(* Logix 5000 project; controller Electronic_Displays vendor 1 type 14 code 65 rev 17.4; software revision 17.01; part 2 of 9 *)
(* tags used below, declared in another part *)
   EDV : LEDSIGN;
   ENABLE : DINT;

ADD_ON_INSTRUCTION ExpertSign   (* revision 1.0, ExecuteEnableInFalse *)
// Expert Mode
// Send Your Own
// Packets
// Revision note:
// Original Release
// 11-01-2012
// c.elston
VAR_IN_OUT
   ExpertPacket1 : STRING; {required}   // Raw Packet1 to be sent to sign for the expert users. (82 Characters max)
   ExpertPacket2 : STRING; {required}   // Raw Packet2 to be sent to sign for the expert users. (82 Characters max)
   ExpertPacket3 : STRING; {required}   // Raw Packet3 to be sent to sign for the expert users. (82 Characters max)
   ExpertPacket4 : STRING; {required}   // Raw Packet4 to be sent to sign for the expert users. (82 Characters max)
   ExpertPacket5 : STRING; {required}   // Raw Packet5 to be sent to sign for the expert users. (82 Characters max)
   ExpertPacket6 : STRING; {required}   // Raw Packet6 to be sent to sign for the expert users. (82 Characters max)
END_VAR
VAR_OUTPUT
   EN : BOOL; {visible}   // Instruction Interface Enable Bit
   DN : BOOL; {visible}   // Instruction Interface Done Bit
   ER : BOOL; {visible}   // Instruction Interface Error Bit
   IP : BOOL; {visible}   // Instruction Interface InProcess Bit
END_VAR
VAR_IN_OUT
   map_SignInput : SINT[32]; {required}   // Ethernet/IP LEDSIGN.I Data I/O Mapping
   map_SignOutput : SINT[496]; {required}   // Ethernet/IP LEDSIGN.O Data I/O Mapping
   Packet1Sent : STRING; {required}   // The actual packet sent to the sign (Packet1)
   Packet2Sent : STRING; {required}   // The actual packet sent to the sign (Packet2)
   Packet3Sent : STRING; {required}   // The actual packet sent to the sign (Packet3)
   Packet4Sent : STRING; {required}   // The actual packet sent to the sign (Packet4)
   Packet5Sent : STRING; {required}   // The actual packet sent to the sign (Packet5)
   Packet6Sent : STRING; {required}   // The actual packet sent to the sign (Packet6)
END_VAR
VAR
   SEQ : DINT;   // Sequence Number
   OktoCycle : BOOL;   // Ok to Cycle
   InCycle : BOOL;   // Incycle
   Error : BOOL;   // Error
   Enabled : BOOL;   // Enable ON Bit
   Done : BOOL;   // Done
   Disabled : BOOL;   // Disabled OFF Bit
   SignNULL : STRING;
   TotalPacketCount : DINT[7];   // Total Character Count
   Select : DINT;   // Packet Array Select
   PacketMax : DINT := 82;   // Max Packet Count
   PacketCount : DINT[7];
   Packet6Offset : DINT;
   Packet5Offset : DINT;
   Packet4Offset : DINT;
   Packet3Offset : DINT;
   Packet2Offset : DINT;
   Packet1Offset : DINT;
   Packet : STRING[7];   // Packet Array to send to sign
   SignExpertPacket6 : STRING;
   SignExpertPacket5 : STRING;
   SignExpertPacket4 : STRING;
   SignExpertPacket3 : STRING;
   SignExpertPacket2 : STRING;
   SignExpertPacket1 : STRING;
END_VAR

ROUTINE EnableInFalse   (* ladder *)
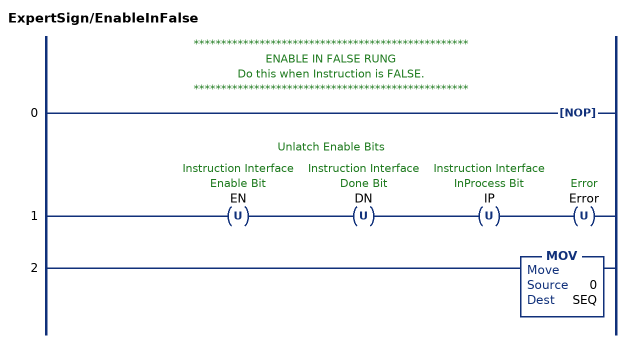
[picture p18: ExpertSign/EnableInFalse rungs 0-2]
   // **************************************************
   // ENABLE IN FALSE RUNG
   // Do this when Instruction is FALSE.
   // **************************************************
   0: NOP();
   // Unlatch Enable Bits
   1: OTU(EN)OTU(DN)OTU(IP)OTU(Error);
   2: MOV(0,SEQ);
END_ROUTINE

ROUTINE Logic   (* ladder *)
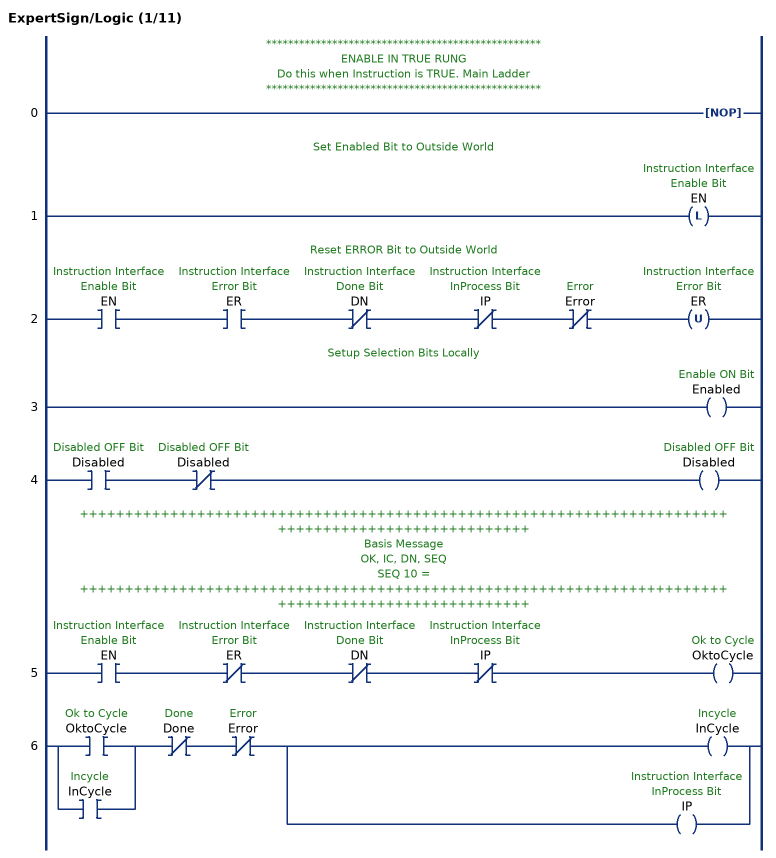
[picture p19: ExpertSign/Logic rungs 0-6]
   // **************************************************
   // ENABLE IN TRUE RUNG
   // Do this when Instruction is TRUE. Main Ladder
   // **************************************************
   0: NOP();
   // Set Enabled Bit to Outside World
   1: OTL(EN);
   // Reset ERROR Bit to Outside World
   2: XIC(EN)XIC(ER)XIO(DN)XIO(IP)XIO(Error)OTU(ER);
   // Setup Selection Bits Locally
   3: OTE(Enabled);
   4: XIC(Disabled)XIO(Disabled)OTE(Disabled);
   // ++++++++++++++++++++++++++++++++++++++++++++++++++++++++++++++++++++++++++++++++++++++++++++++++++++
   // Basis Message
   // OK, IC, DN, SEQ
   // SEQ 10 =
   // ++++++++++++++++++++++++++++++++++++++++++++++++++++++++++++++++++++++++++++++++++++++++++++++++++++
   5: XIC(EN)XIO(ER)XIO(DN)XIO(IP)OTE(OktoCycle);
   6: [XIC(OktoCycle) ,XIC(InCycle) ]XIO(Done)XIO(Error)[OTE(InCycle) ,OTE(IP) ];
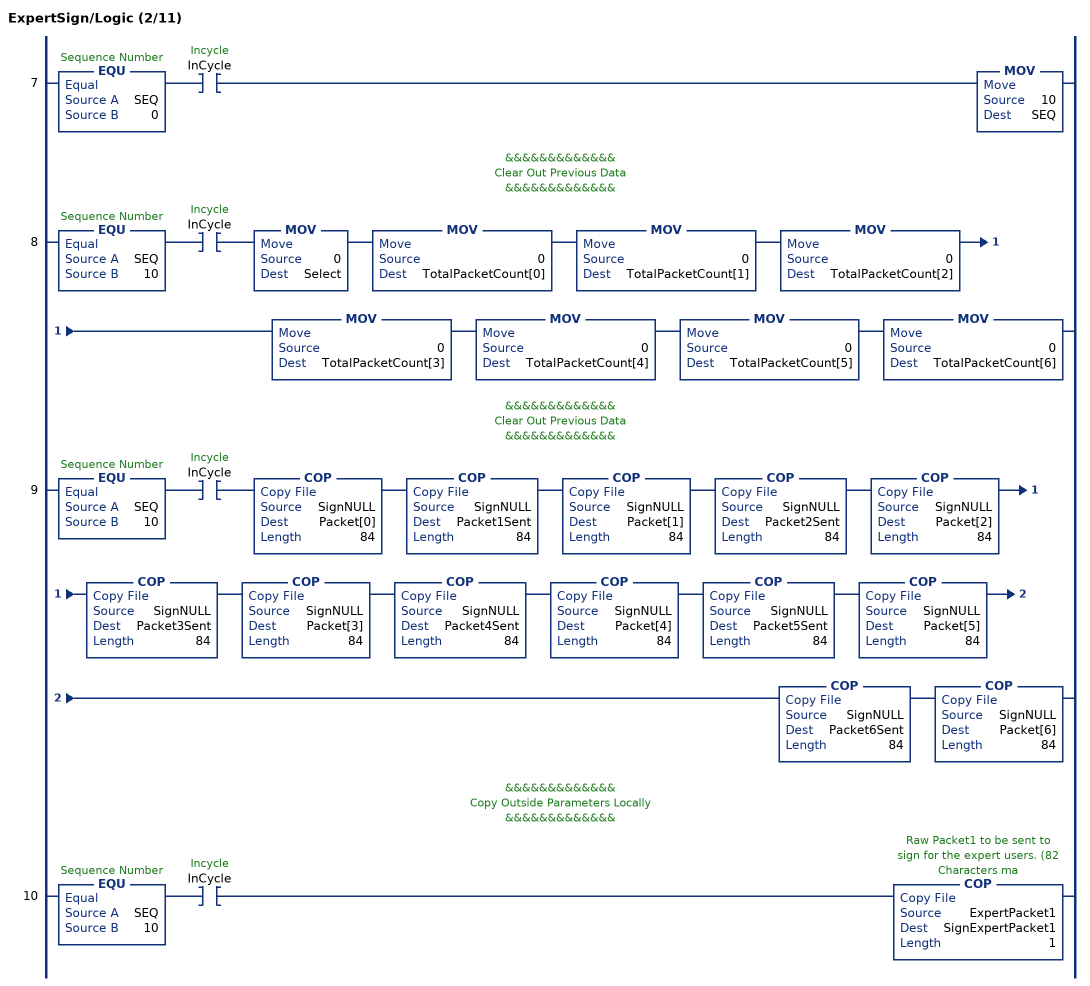
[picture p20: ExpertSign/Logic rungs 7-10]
   7: EQU(SEQ,0)XIC(InCycle)MOV(10,SEQ);
   // &&&&&&&&&&&&&
   // Clear Out Previous Data
   // &&&&&&&&&&&&&
   8: EQU(SEQ,10)XIC(InCycle)MOV(0,Select)MOV(0,TotalPacketCount[0])MOV(0,TotalPacketCount[1])MOV(0,TotalPacketCount[2])MOV(0,TotalPacketCount[3])MOV(0,TotalPacketCount[4])MOV(0,TotalPacketCount[5])MOV(0,TotalPacketCount[6]);
   // &&&&&&&&&&&&&
   // Clear Out Previous Data
   // &&&&&&&&&&&&&
   9: EQU(SEQ,10)XIC(InCycle)COP(SignNULL,Packet[0],84)COP(SignNULL,Packet1Sent,84)COP(SignNULL,Packet[1],84)COP(SignNULL,Packet2Sent,84)COP(SignNULL,Packet[2],84)COP(SignNULL,Packet3Sent,84)COP(SignNULL,Packet[3],84)COP(SignNULL,Packet4Sent,84)COP(SignNULL,Packet[4],84)COP(SignNULL,Packet5Sent,84)COP(SignNULL,Packet[5],84)COP(SignNULL,Packet6Sent,84)COP(SignNULL,Packet[6],84);
   // &&&&&&&&&&&&&
   // Copy Outside Parameters Locally
   // &&&&&&&&&&&&&
   10: EQU(SEQ,10)XIC(InCycle)COP(ExpertPacket1,SignExpertPacket1,1);
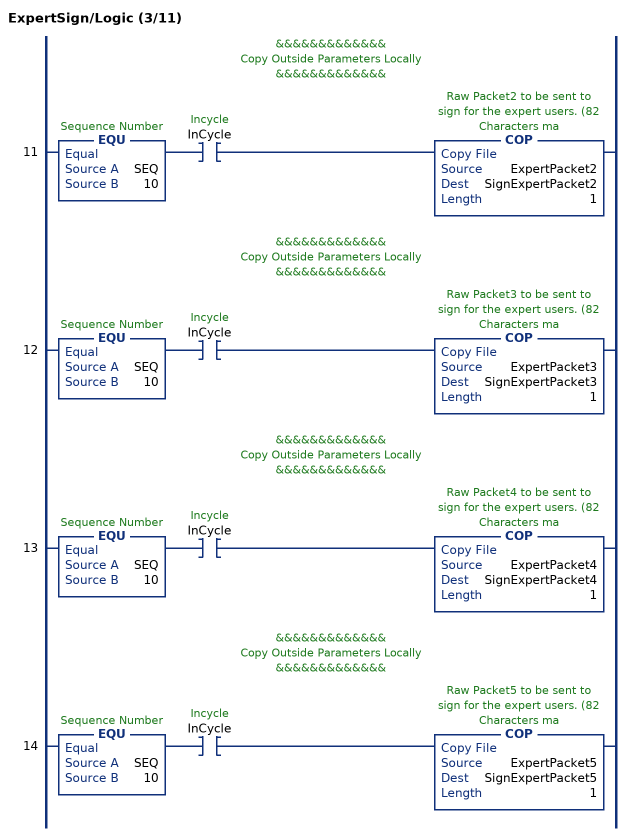
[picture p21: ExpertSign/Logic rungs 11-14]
   // &&&&&&&&&&&&&
   // Copy Outside Parameters Locally
   // &&&&&&&&&&&&&
   11: EQU(SEQ,10)XIC(InCycle)COP(ExpertPacket2,SignExpertPacket2,1);
   // &&&&&&&&&&&&&
   // Copy Outside Parameters Locally
   // &&&&&&&&&&&&&
   12: EQU(SEQ,10)XIC(InCycle)COP(ExpertPacket3,SignExpertPacket3,1);
   // &&&&&&&&&&&&&
   // Copy Outside Parameters Locally
   // &&&&&&&&&&&&&
   13: EQU(SEQ,10)XIC(InCycle)COP(ExpertPacket4,SignExpertPacket4,1);
   // &&&&&&&&&&&&&
   // Copy Outside Parameters Locally
   // &&&&&&&&&&&&&
   14: EQU(SEQ,10)XIC(InCycle)COP(ExpertPacket5,SignExpertPacket5,1);
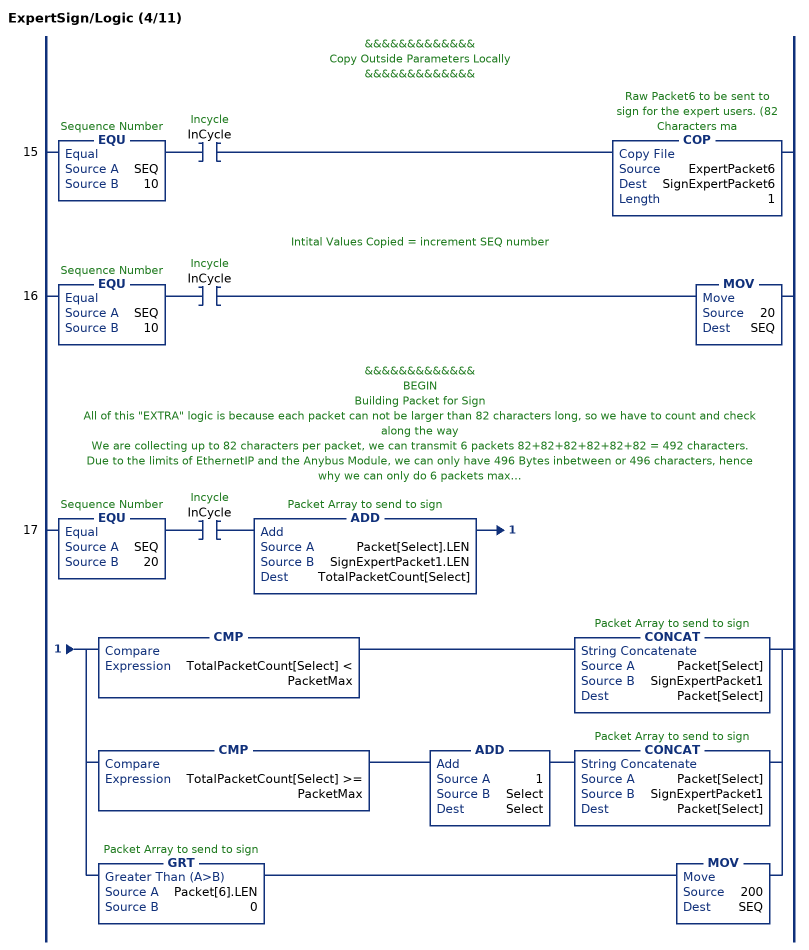
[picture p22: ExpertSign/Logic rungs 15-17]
   // &&&&&&&&&&&&&
   // Copy Outside Parameters Locally
   // &&&&&&&&&&&&&
   15: EQU(SEQ,10)XIC(InCycle)COP(ExpertPacket6,SignExpertPacket6,1);
   // Intital Values Copied = increment SEQ number
   16: EQU(SEQ,10)XIC(InCycle)MOV(20,SEQ);
   // &&&&&&&&&&&&&
   // BEGIN
   // Building Packet for Sign
   // All of this "EXTRA" logic is because each packet can not be larger than 82 characters long, so we have to count and check along the way
   // We are collecting up to 82 characters per packet, we can transmit 6 packets 82+82+82+82+82+82 = 492 characters.
   // Due to the limits of EthernetIP and the Anybus Module, we can only have 496 Bytes inbetween or 496 characters, hence why we can only do 6 packets max.
   // Once we exceed this, we will fault and ERROR trap any windy typing people.
   // In this instruction below, it's so small, we are only using 3 packets max.
   // &&&&&&&&&&&&&
   17: EQU(SEQ,20)XIC(InCycle)ADD(Packet[Select].LEN,SignExpertPacket1.LEN,TotalPacketCount[Select])[CMP(TotalPacketCount[Select] < PacketMax) CONCAT(Packet[Select],SignExpertPacket1,Packet[Select]) ,CMP(TotalPacketCount[Select] >= PacketMax) ADD(1,Select,Select) CONCAT(Packet[Select],SignExpertPacket1,Packet[Select]) ,GRT(Packet[6].LEN,0) MOV(200,SEQ) ];
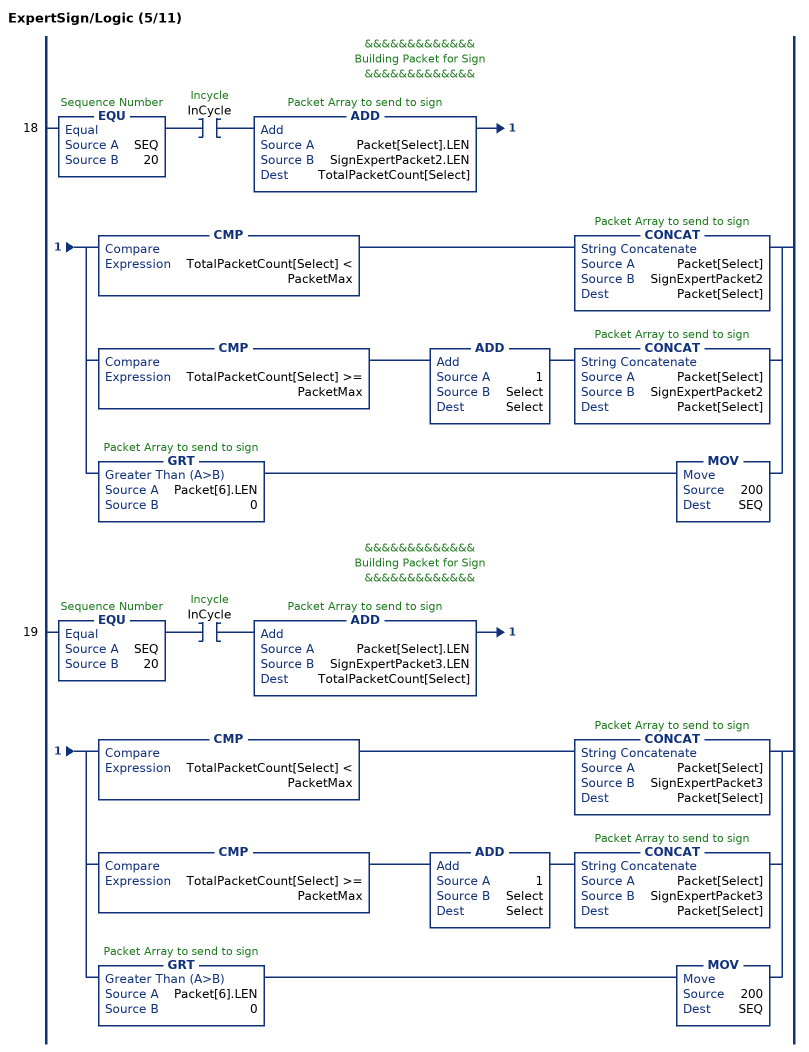
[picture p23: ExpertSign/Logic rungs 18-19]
   // &&&&&&&&&&&&&
   // Building Packet for Sign
   // &&&&&&&&&&&&&
   18: EQU(SEQ,20)XIC(InCycle)ADD(Packet[Select].LEN,SignExpertPacket2.LEN,TotalPacketCount[Select])[CMP(TotalPacketCount[Select] < PacketMax) CONCAT(Packet[Select],SignExpertPacket2,Packet[Select]) ,CMP(TotalPacketCount[Select] >= PacketMax) ADD(1,Select,Select) CONCAT(Packet[Select],SignExpertPacket2,Packet[Select]) ,GRT(Packet[6].LEN,0) MOV(200,SEQ) ];
   // &&&&&&&&&&&&&
   // Building Packet for Sign
   // &&&&&&&&&&&&&
   19: EQU(SEQ,20)XIC(InCycle)ADD(Packet[Select].LEN,SignExpertPacket3.LEN,TotalPacketCount[Select])[CMP(TotalPacketCount[Select] < PacketMax) CONCAT(Packet[Select],SignExpertPacket3,Packet[Select]) ,CMP(TotalPacketCount[Select] >= PacketMax) ADD(1,Select,Select) CONCAT(Packet[Select],SignExpertPacket3,Packet[Select]) ,GRT(Packet[6].LEN,0) MOV(200,SEQ) ];
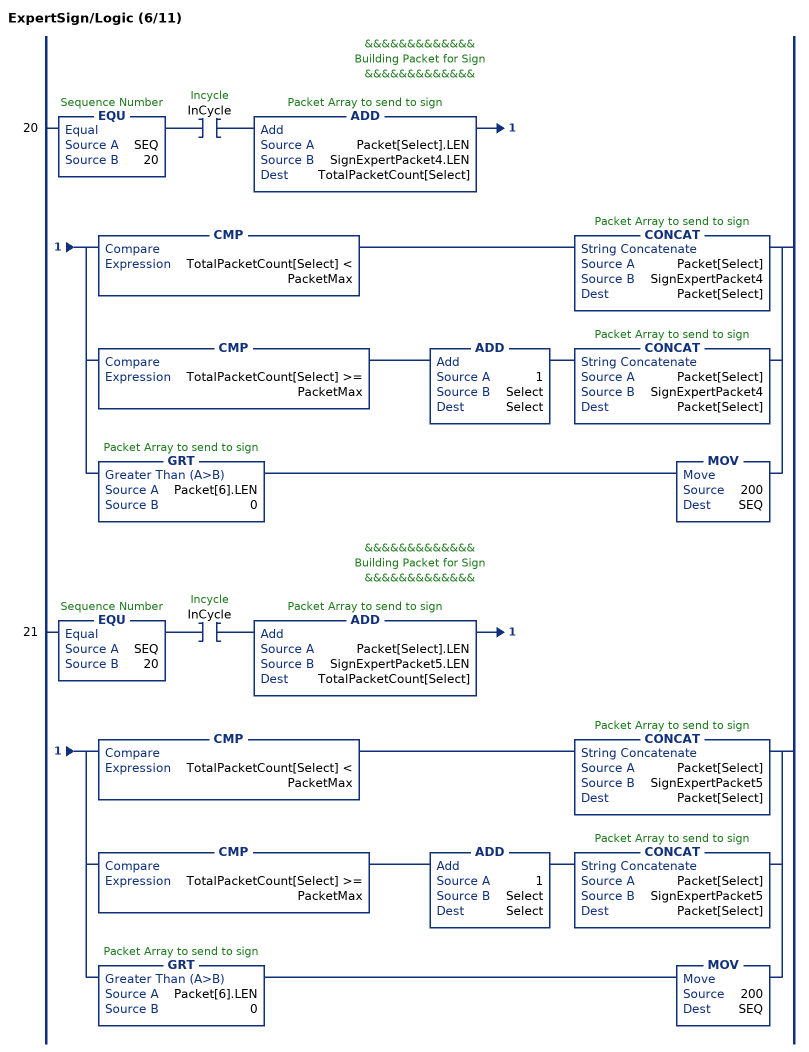
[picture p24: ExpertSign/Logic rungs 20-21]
   // &&&&&&&&&&&&&
   // Building Packet for Sign
   // &&&&&&&&&&&&&
   20: EQU(SEQ,20)XIC(InCycle)ADD(Packet[Select].LEN,SignExpertPacket4.LEN,TotalPacketCount[Select])[CMP(TotalPacketCount[Select] < PacketMax) CONCAT(Packet[Select],SignExpertPacket4,Packet[Select]) ,CMP(TotalPacketCount[Select] >= PacketMax) ADD(1,Select,Select) CONCAT(Packet[Select],SignExpertPacket4,Packet[Select]) ,GRT(Packet[6].LEN,0) MOV(200,SEQ) ];
   // &&&&&&&&&&&&&
   // Building Packet for Sign
   // &&&&&&&&&&&&&
   21: EQU(SEQ,20)XIC(InCycle)ADD(Packet[Select].LEN,SignExpertPacket5.LEN,TotalPacketCount[Select])[CMP(TotalPacketCount[Select] < PacketMax) CONCAT(Packet[Select],SignExpertPacket5,Packet[Select]) ,CMP(TotalPacketCount[Select] >= PacketMax) ADD(1,Select,Select) CONCAT(Packet[Select],SignExpertPacket5,Packet[Select]) ,GRT(Packet[6].LEN,0) MOV(200,SEQ) ];
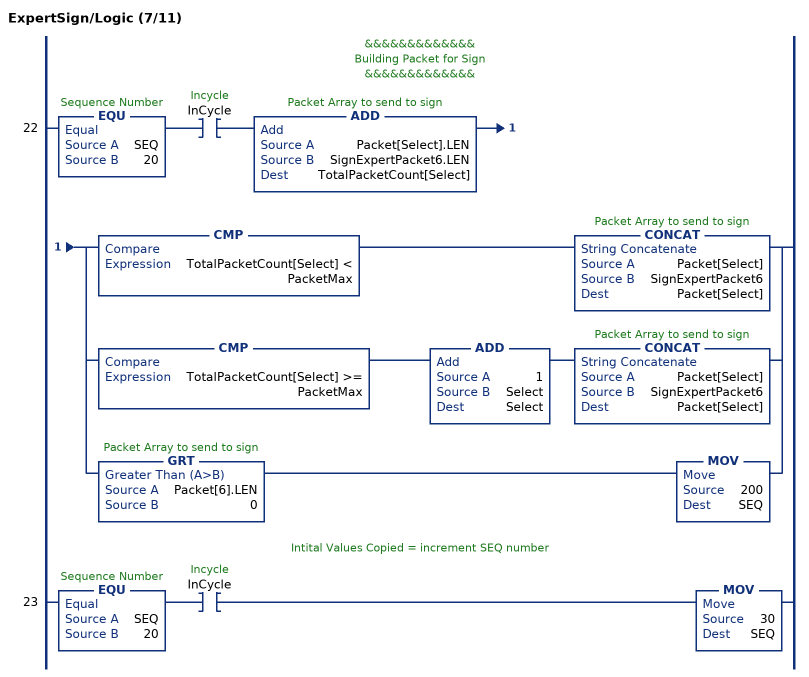
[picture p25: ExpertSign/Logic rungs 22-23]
   // &&&&&&&&&&&&&
   // Building Packet for Sign
   // &&&&&&&&&&&&&
   22: EQU(SEQ,20)XIC(InCycle)ADD(Packet[Select].LEN,SignExpertPacket6.LEN,TotalPacketCount[Select])[CMP(TotalPacketCount[Select] < PacketMax) CONCAT(Packet[Select],SignExpertPacket6,Packet[Select]) ,CMP(TotalPacketCount[Select] >= PacketMax) ADD(1,Select,Select) CONCAT(Packet[Select],SignExpertPacket6,Packet[Select]) ,GRT(Packet[6].LEN,0) MOV(200,SEQ) ];
   // Intital Values Copied = increment SEQ number
   23: EQU(SEQ,20)XIC(InCycle)MOV(30,SEQ);
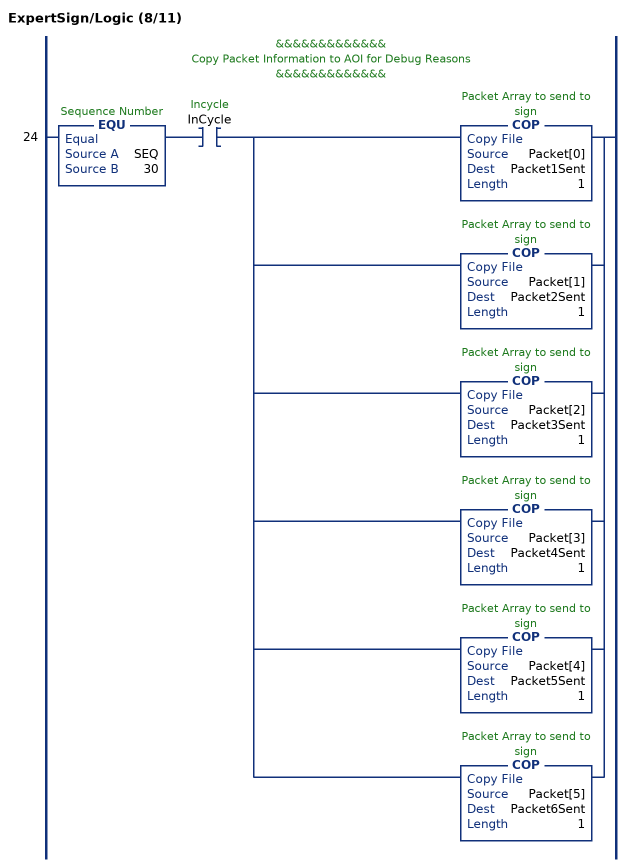
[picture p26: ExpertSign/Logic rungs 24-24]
   // &&&&&&&&&&&&&
   // Copy Packet Information to AOI for Debug Reasons
   // &&&&&&&&&&&&&
   24: EQU(SEQ,30)XIC(InCycle)[COP(Packet[0],Packet1Sent,1) ,COP(Packet[1],Packet2Sent,1) ,COP(Packet[2],Packet3Sent,1) ,COP(Packet[3],Packet4Sent,1) ,COP(Packet[4],Packet5Sent,1) ,COP(Packet[5],Packet6Sent,1) ];
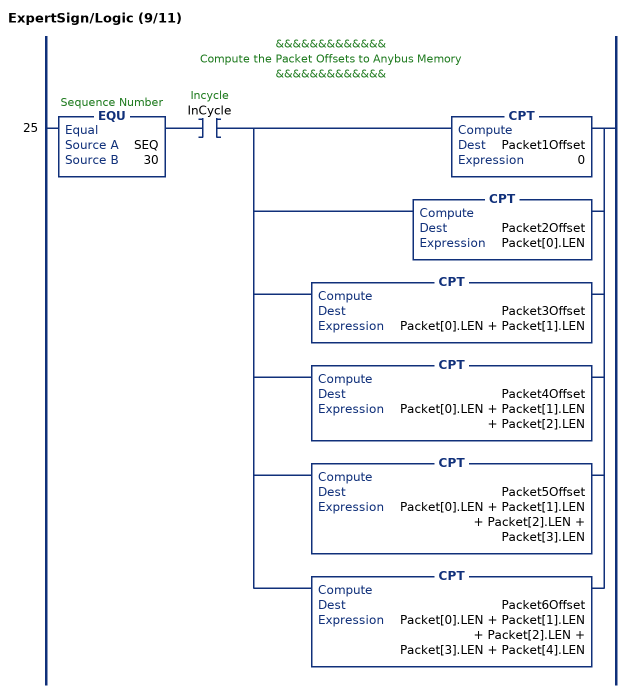
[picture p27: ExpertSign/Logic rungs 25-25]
   // &&&&&&&&&&&&&
   // Compute the Packet Offsets to Anybus Memory
   // &&&&&&&&&&&&&
   25: EQU(SEQ,30)XIC(InCycle)[CPT(Packet1Offset,0) ,CPT(Packet2Offset,Packet[0].LEN) ,CPT(Packet3Offset,Packet[0].LEN + Packet[1].LEN) ,CPT(Packet4Offset,Packet[0].LEN + Packet[1].LEN + Packet[2].LEN) ,CPT(Packet5Offset,Packet[0].LEN + Packet[1].LEN + Packet[2].LEN + Packet[3].LEN) ,CPT(Packet6Offset,Packet[0].LEN + Packet[1].LEN + Packet[2].LEN + Packet[3].LEN + Packet[4].LEN) ];
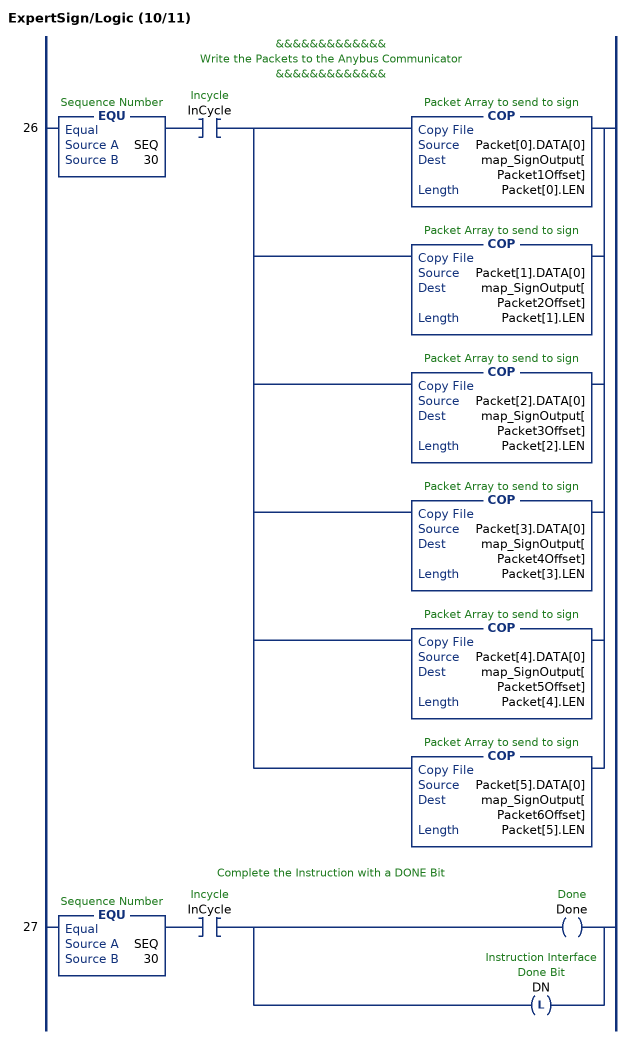
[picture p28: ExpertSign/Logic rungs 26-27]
   // &&&&&&&&&&&&&
   // Write the Packets to the Anybus Communicator
   // &&&&&&&&&&&&&
   26: EQU(SEQ,30)XIC(InCycle)[COP(Packet[0].DATA[0],map_SignOutput[Packet1Offset],Packet[0].LEN) ,COP(Packet[1].DATA[0],map_SignOutput[Packet2Offset],Packet[1].LEN) ,COP(Packet[2].DATA[0],map_SignOutput[Packet3Offset],Packet[2].LEN) ,COP(Packet[3].DATA[0],map_SignOutput[Packet4Offset],Packet[3].LEN) ,COP(Packet[4].DATA[0],map_SignOutput[Packet5Offset],Packet[4].LEN) ,COP(Packet[5].DATA[0],map_SignOutput[Packet6Offset],Packet[5].LEN) ];
   // Complete the Instruction with a DONE Bit
   27: EQU(SEQ,30)XIC(InCycle)[OTE(Done) ,OTL(DN) ];
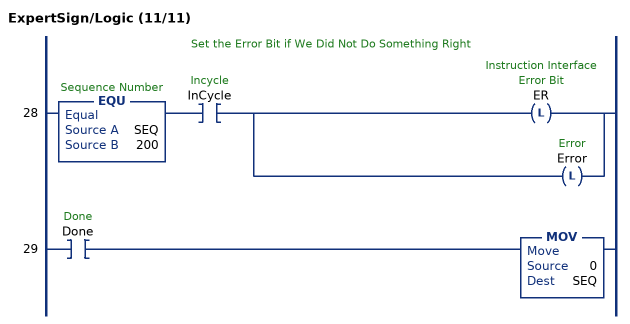
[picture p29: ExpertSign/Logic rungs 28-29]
   // Set the Error Bit if We Did Not Do Something Right
   28: EQU(SEQ,200)XIC(InCycle)[OTL(ER) ,OTL(Error) ];
   29: XIC(Done)MOV(0,SEQ);
END_ROUTINE
END_ADD_ON_INSTRUCTION

ADD_ON_INSTRUCTION NumberSign   (* revision 1.0, ExecuteEnableInFalse *)
// Number Sign
// Send only Numbers
// Revision note:
// Original Release
// 03-30-2013
// c.elston
VAR_IN_OUT
   Address : STRING; {required}   // "01" = address 01 "02" = address 02 etc...(see protocol)
   NumberValue : DINT; {required}   // Actual number value (DINT Format)
END_VAR
VAR_OUTPUT
   EN : BOOL; {visible}   // Instruction Interface Enable Bit
   DN : BOOL; {visible}   // Instruction Interface Done Bit
   ER : BOOL; {visible}   // Instruction Interface Error Bit
   IP : BOOL; {visible}   // Instruction Interface InProcess Bit
END_VAR
VAR_IN_OUT
   map_SignInput : SINT[32]; {required}   // Ethernet/IP LEDSIGN.I Data I/O Mapping
   map_SignOutput : SINT[496]; {required}   // Ethernet/IP LEDSIGN.O Data I/O Mapping
   PacketSent : STRING; {required}   // The actual packet sent to the sign.
END_VAR
VAR
   SEQ : DINT;   // Sequence Number
   OktoCycle : BOOL;   // Ok to Cycle
   InCycle : BOOL;   // Incycle
   Error : BOOL;   // Error
   Enabled : BOOL;   // Enable ON Bit
   Done : BOOL;   // Done
   Disabled : BOOL;   // Disabled OFF Bit
   SignETX : STRING := '$03';   // DO NOT EDIT = $03 the number sign protocol is different than EDV signs
   SignAddress : STRING;
   SignSTX : STRING := '$02';   // DO NOT EDIT = $02 the number sign protocol is different than EDV signs
   SignNULL : STRING;
   TotalPacketCount : DINT[7];   // Total Character Count
   Select : DINT;   // Packet Array Select
   PacketMax : DINT := 82;   // Max Packet Count
   PacketCount : DINT[7];
   Packet6Offset : DINT;
   Packet5Offset : DINT;
   Packet4Offset : DINT;
   Packet3Offset : DINT;
   Packet2Offset : DINT;
   Packet1Offset : DINT;
   Packet : STRING[7];   // Packet Array to send to sign
   SignNumberValue : DINT;
   SignVariable1Value : STRING;
   SignNumberValue1 : STRING;
   SignNumberValueSTRING : STRING;
END_VAR

ROUTINE EnableInFalse   (* ladder *)
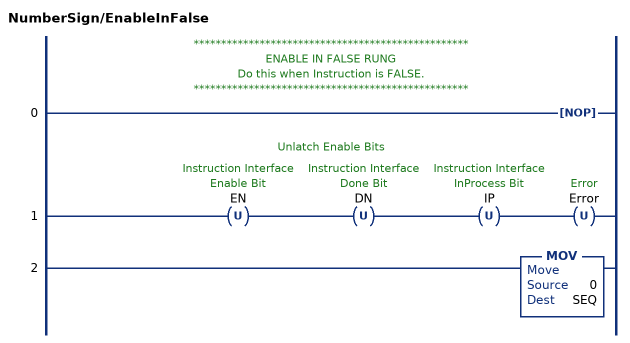
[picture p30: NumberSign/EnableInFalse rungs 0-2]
   // **************************************************
   // ENABLE IN FALSE RUNG
   // Do this when Instruction is FALSE.
   // **************************************************
   0: NOP();
   // Unlatch Enable Bits
   1: OTU(EN)OTU(DN)OTU(IP)OTU(Error);
   2: MOV(0,SEQ);
END_ROUTINE

ROUTINE Logic   (* ladder *)
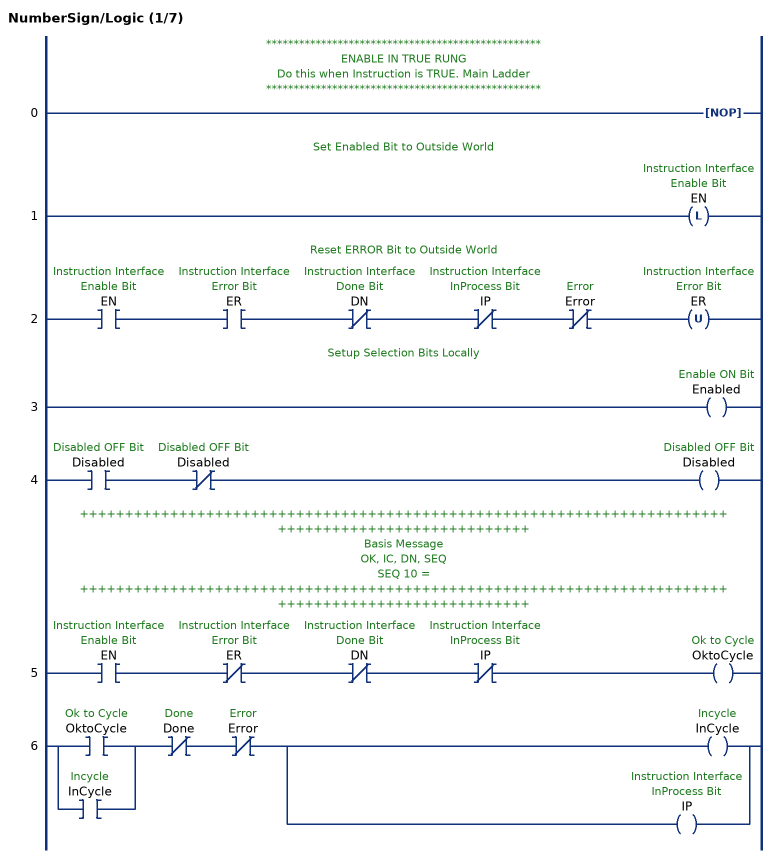
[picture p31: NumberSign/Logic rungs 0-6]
   // **************************************************
   // ENABLE IN TRUE RUNG
   // Do this when Instruction is TRUE. Main Ladder
   // **************************************************
   0: NOP();
   // Set Enabled Bit to Outside World
   1: OTL(EN);
   // Reset ERROR Bit to Outside World
   2: XIC(EN)XIC(ER)XIO(DN)XIO(IP)XIO(Error)OTU(ER);
   // Setup Selection Bits Locally
   3: OTE(Enabled);
   4: XIC(Disabled)XIO(Disabled)OTE(Disabled);
   // ++++++++++++++++++++++++++++++++++++++++++++++++++++++++++++++++++++++++++++++++++++++++++++++++++++
   // Basis Message
   // OK, IC, DN, SEQ
   // SEQ 10 =
   // ++++++++++++++++++++++++++++++++++++++++++++++++++++++++++++++++++++++++++++++++++++++++++++++++++++
   5: XIC(EN)XIO(ER)XIO(DN)XIO(IP)OTE(OktoCycle);
   6: [XIC(OktoCycle) ,XIC(InCycle) ]XIO(Done)XIO(Error)[OTE(InCycle) ,OTE(IP) ];
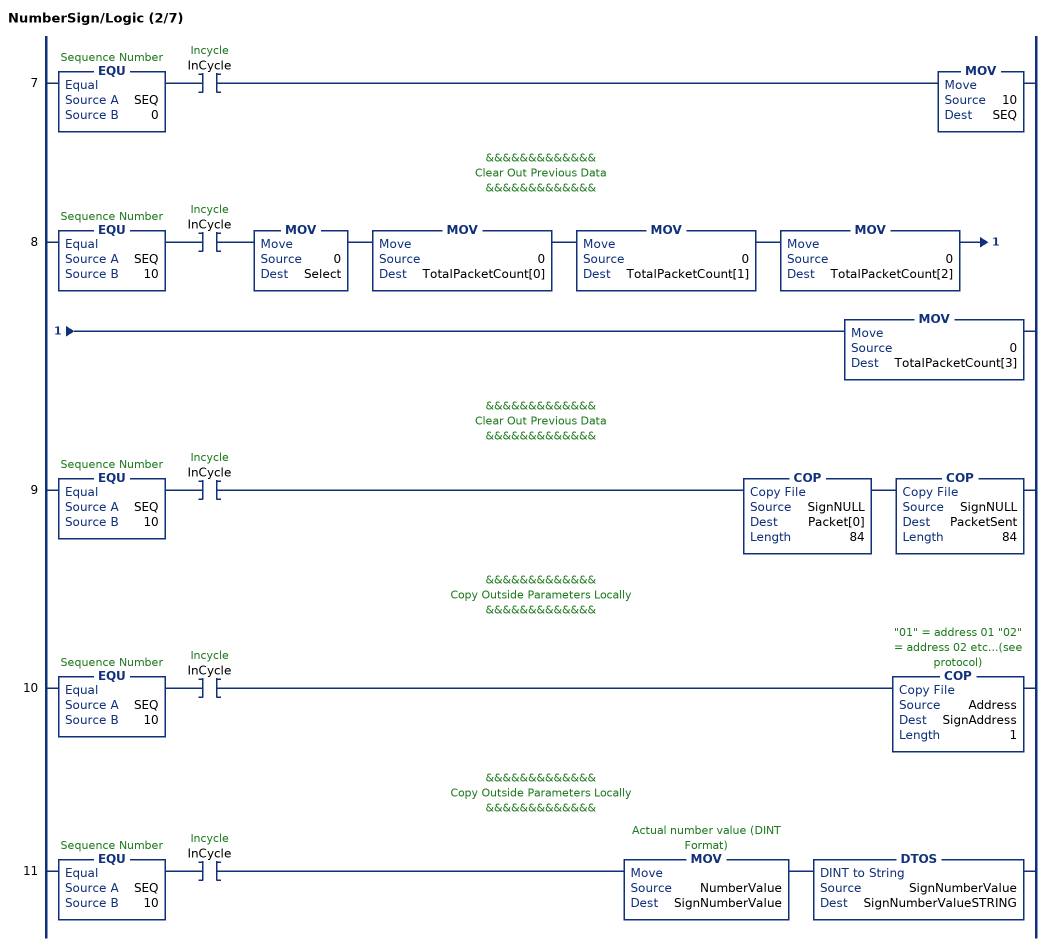
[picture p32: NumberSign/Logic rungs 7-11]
   7: EQU(SEQ,0)XIC(InCycle)MOV(10,SEQ);
   // &&&&&&&&&&&&&
   // Clear Out Previous Data
   // &&&&&&&&&&&&&
   8: EQU(SEQ,10)XIC(InCycle)MOV(0,Select)MOV(0,TotalPacketCount[0])MOV(0,TotalPacketCount[1])MOV(0,TotalPacketCount[2])MOV(0,TotalPacketCount[3]);
   // &&&&&&&&&&&&&
   // Clear Out Previous Data
   // &&&&&&&&&&&&&
   9: EQU(SEQ,10)XIC(InCycle)COP(SignNULL,Packet[0],84)COP(SignNULL,PacketSent,84);
   // &&&&&&&&&&&&&
   // Copy Outside Parameters Locally
   // &&&&&&&&&&&&&
   10: EQU(SEQ,10)XIC(InCycle)COP(Address,SignAddress,1);
   // &&&&&&&&&&&&&
   // Copy Outside Parameters Locally
   // &&&&&&&&&&&&&
   11: EQU(SEQ,10)XIC(InCycle)MOV(NumberValue,SignNumberValue)DTOS(SignNumberValue,SignNumberValueSTRING);
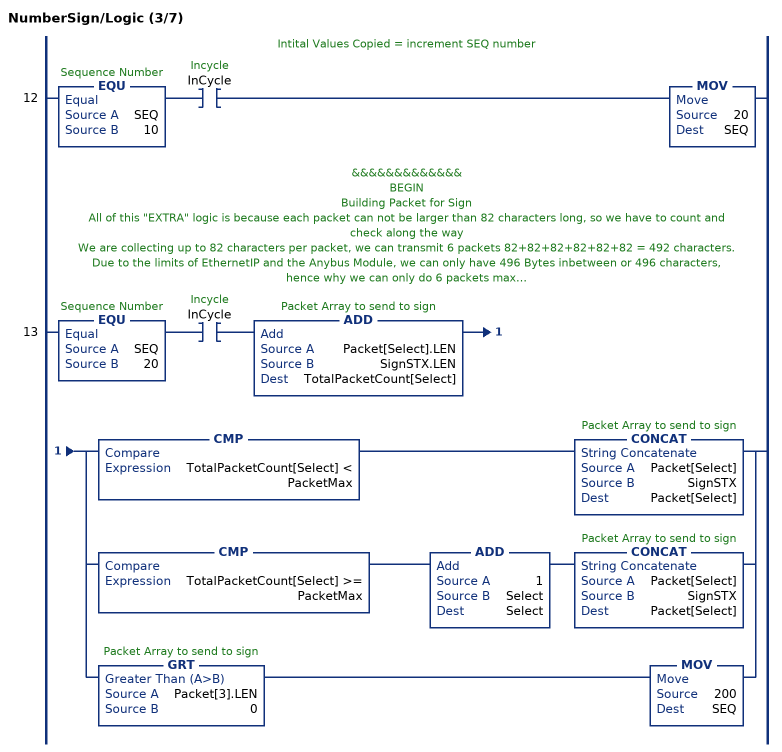
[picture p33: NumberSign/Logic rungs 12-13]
   // Intital Values Copied = increment SEQ number
   12: EQU(SEQ,10)XIC(InCycle)MOV(20,SEQ);
   // &&&&&&&&&&&&&
   // BEGIN
   // Building Packet for Sign
   // All of this "EXTRA" logic is because each packet can not be larger than 82 characters long, so we have to count and check along the way
   // We are collecting up to 82 characters per packet, we can transmit 6 packets 82+82+82+82+82+82 = 492 characters.
   // Due to the limits of EthernetIP and the Anybus Module, we can only have 496 Bytes inbetween or 496 characters, hence why we can only do 6 packets max.
   // Once we exceed this, we will fault and ERROR trap any windy typing people.
   // In this instruction below, it's so small, we are only using 3 packets max.
   // &&&&&&&&&&&&&
   13: EQU(SEQ,20)XIC(InCycle)ADD(Packet[Select].LEN,SignSTX.LEN,TotalPacketCount[Select])[CMP(TotalPacketCount[Select] < PacketMax) CONCAT(Packet[Select],SignSTX,Packet[Select]) ,CMP(TotalPacketCount[Select] >= PacketMax) ADD(1,Select,Select) CONCAT(Packet[Select],SignSTX,Packet[Select]) ,GRT(Packet[3].LEN,0) MOV(200,SEQ) ];
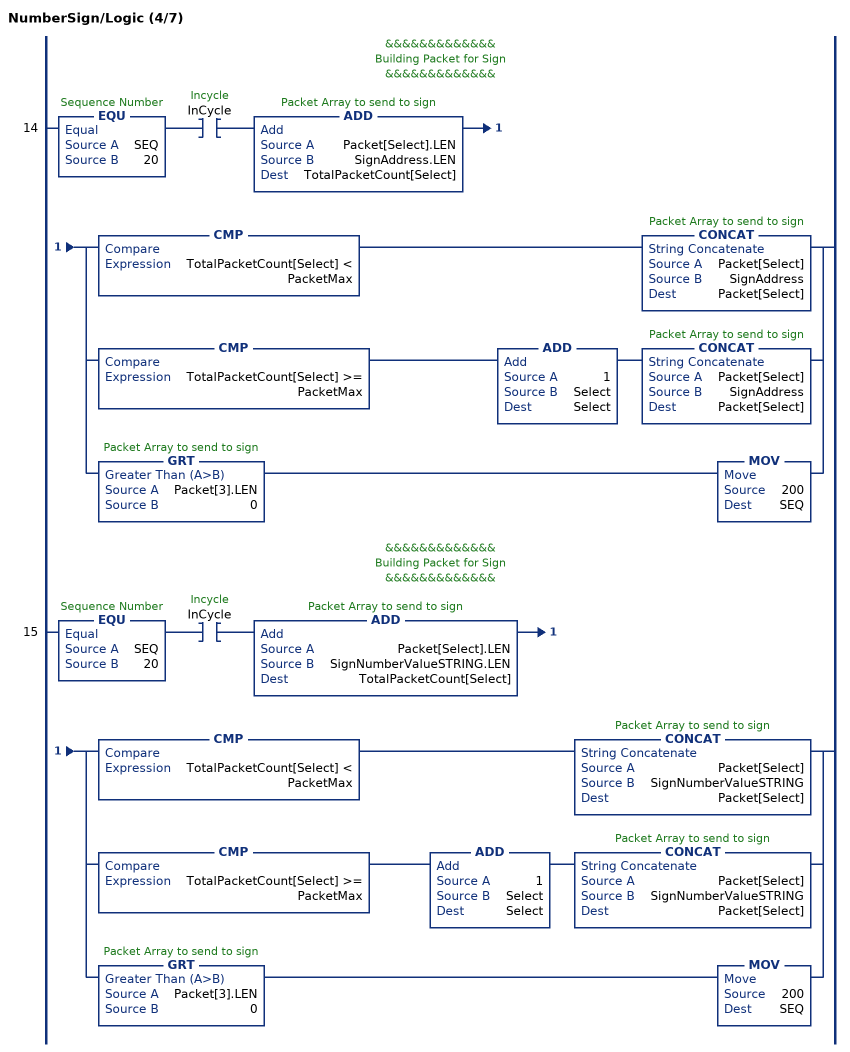
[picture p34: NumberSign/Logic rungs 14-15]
   // &&&&&&&&&&&&&
   // Building Packet for Sign
   // &&&&&&&&&&&&&
   14: EQU(SEQ,20)XIC(InCycle)ADD(Packet[Select].LEN,SignAddress.LEN,TotalPacketCount[Select])[CMP(TotalPacketCount[Select] < PacketMax) CONCAT(Packet[Select],SignAddress,Packet[Select]) ,CMP(TotalPacketCount[Select] >= PacketMax) ADD(1,Select,Select) CONCAT(Packet[Select],SignAddress,Packet[Select]) ,GRT(Packet[3].LEN,0) MOV(200,SEQ) ];
   // &&&&&&&&&&&&&
   // Building Packet for Sign
   // &&&&&&&&&&&&&
   15: EQU(SEQ,20)XIC(InCycle)ADD(Packet[Select].LEN,SignNumberValueSTRING.LEN,TotalPacketCount[Select])[CMP(TotalPacketCount[Select] < PacketMax) CONCAT(Packet[Select],SignNumberValueSTRING,Packet[Select]) ,CMP(TotalPacketCount[Select] >= PacketMax) ADD(1,Select,Select) CONCAT(Packet[Select],SignNumberValueSTRING,Packet[Select]) ,GRT(Packet[3].LEN,0) MOV(200,SEQ) ];
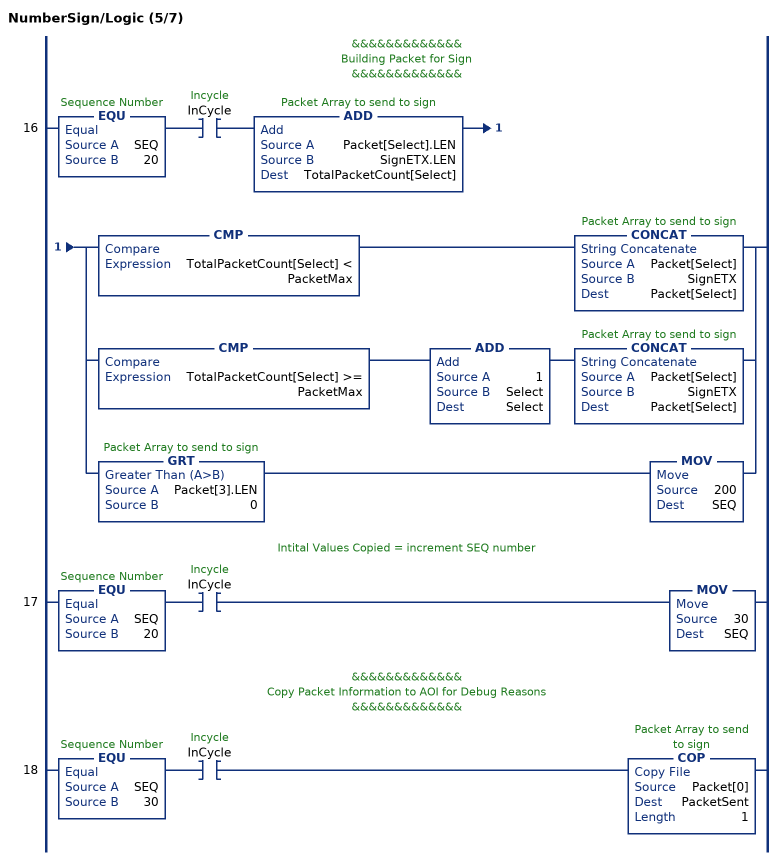
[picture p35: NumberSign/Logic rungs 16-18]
   // &&&&&&&&&&&&&
   // Building Packet for Sign
   // &&&&&&&&&&&&&
   16: EQU(SEQ,20)XIC(InCycle)ADD(Packet[Select].LEN,SignETX.LEN,TotalPacketCount[Select])[CMP(TotalPacketCount[Select] < PacketMax) CONCAT(Packet[Select],SignETX,Packet[Select]) ,CMP(TotalPacketCount[Select] >= PacketMax) ADD(1,Select,Select) CONCAT(Packet[Select],SignETX,Packet[Select]) ,GRT(Packet[3].LEN,0) MOV(200,SEQ) ];
   // Intital Values Copied = increment SEQ number
   17: EQU(SEQ,20)XIC(InCycle)MOV(30,SEQ);
   // &&&&&&&&&&&&&
   // Copy Packet Information to AOI for Debug Reasons
   // &&&&&&&&&&&&&
   18: EQU(SEQ,30)XIC(InCycle)COP(Packet[0],PacketSent,1);
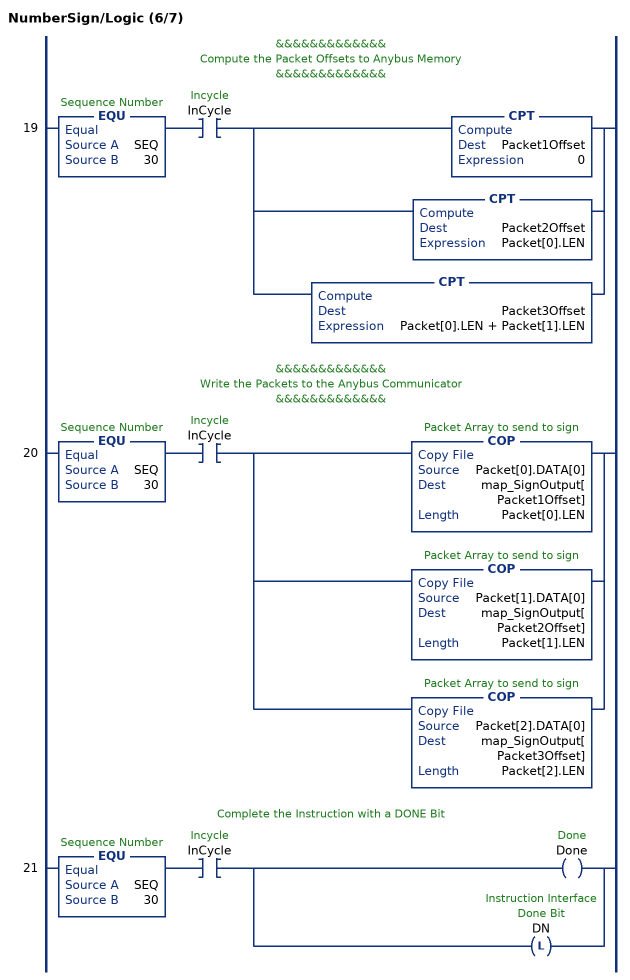
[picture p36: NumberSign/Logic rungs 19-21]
   // &&&&&&&&&&&&&
   // Compute the Packet Offsets to Anybus Memory
   // &&&&&&&&&&&&&
   19: EQU(SEQ,30)XIC(InCycle)[CPT(Packet1Offset,0) ,CPT(Packet2Offset,Packet[0].LEN) ,CPT(Packet3Offset,Packet[0].LEN + Packet[1].LEN) ];
   // &&&&&&&&&&&&&
   // Write the Packets to the Anybus Communicator
   // &&&&&&&&&&&&&
   20: EQU(SEQ,30)XIC(InCycle)[COP(Packet[0].DATA[0],map_SignOutput[Packet1Offset],Packet[0].LEN) ,COP(Packet[1].DATA[0],map_SignOutput[Packet2Offset],Packet[1].LEN) ,COP(Packet[2].DATA[0],map_SignOutput[Packet3Offset],Packet[2].LEN) ];
   // Complete the Instruction with a DONE Bit
   21: EQU(SEQ,30)XIC(InCycle)[OTE(Done) ,OTL(DN) ];
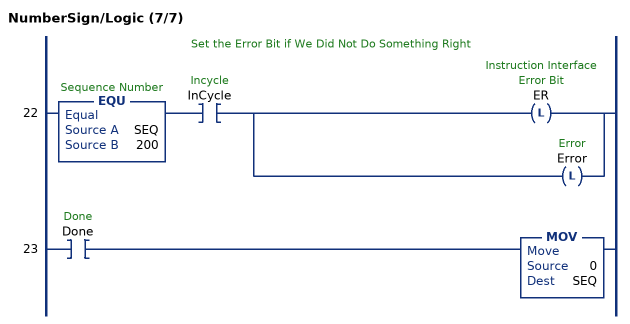
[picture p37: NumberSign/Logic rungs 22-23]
   // Set the Error Bit if We Did Not Do Something Right
   22: EQU(SEQ,200)XIC(InCycle)[OTL(ER) ,OTL(Error) ];
   23: XIC(Done)MOV(0,SEQ);
END_ROUTINE
END_ADD_ON_INSTRUCTION
